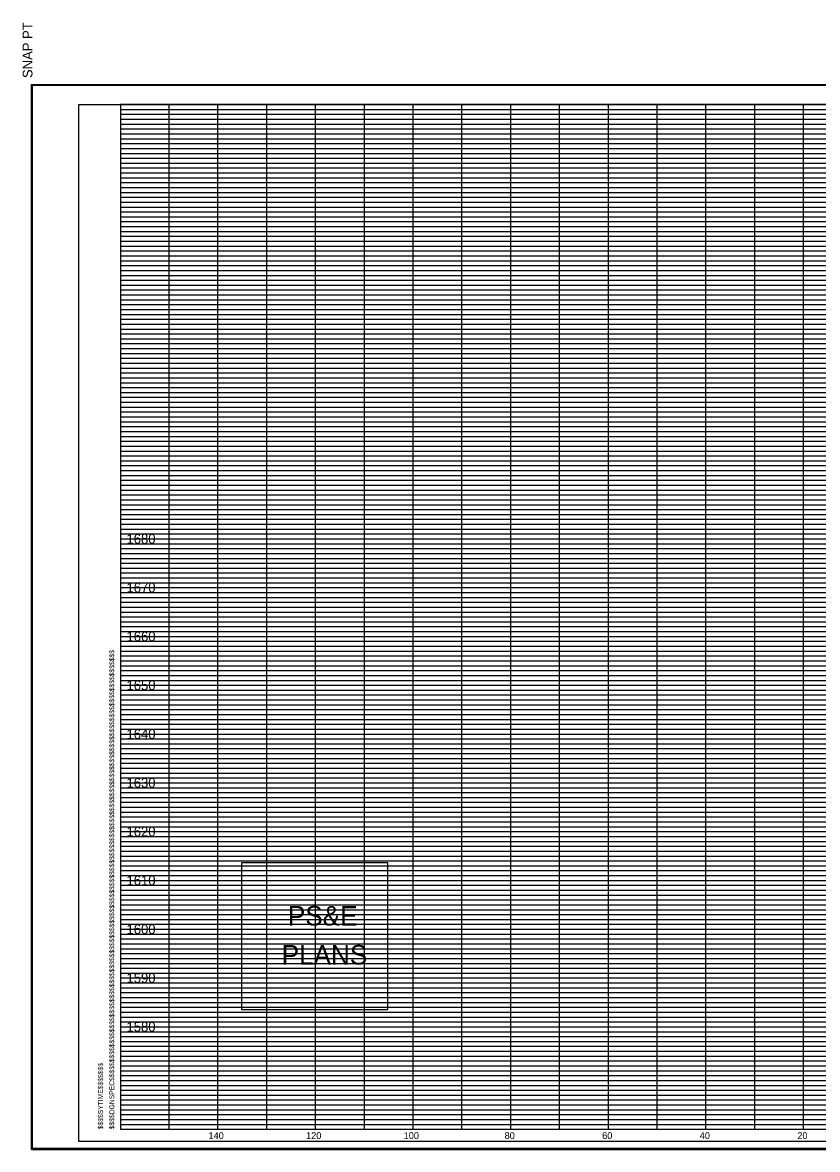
# Model space of a CAD drawing. Extents: x 980 to 1324, y 978 to 1767.
# Drawn here: x 979.9 to 1142.9, y 1265.9 to 1496.8 of the extents above; entities that cross this region are included whole.
import ezdxf

# ---------------------------------------------------------------- set-up
doc = ezdxf.new("R2010")
doc.units = 0
for name, color, linetype in [('DESIGN - SHEET - Corner Text', 7, 'Continuous'), ('DESIGN - SHEET - Light Grid', 7, 'Continuous'), ('DESIGN - SHEET - Linework', 7, 'Continuous'), ('DESIGN - SHEET - Plot Shape', 7, 'Continuous'), ('DESIGN - TYPICAL - Finished Grade and Subgrade', 7, 'Continuous')]:
    doc.layers.add(name, color=color, linetype=linetype)

# ---------------------------------------------------------------- blocks, each defined once
blk = doc.blocks.new('XSTSHT')
at = {"layer": 'DESIGN - SHEET - Light Grid'}
for p, q in [((0, 20.9), (8, 20.9)), ((0, 20.8), (8, 20.8)), ((8, 20.9), (16, 20.9)), ((8, 20.8), (16, 20.8)), ((0, 20.7), (8, 20.7)), ((0, 20.6), (8, 20.6)), ((8, 20.7), (16, 20.7)), ((8, 20.6), (16, 20.6)), ((0, 20.5), (8, 20.5)), ((0, 20.4), (8, 20.4)), ((8, 20.5), (16, 20.5)), ((8, 20.4), (16, 20.4)), ((0, 20.3), (8, 20.3)), ((0, 20.2), (8, 20.2)), ((0, 20.1), (8, 20.1)), ((8, 20.3), (16, 20.3)), ((8, 20.2), (16, 20.2)), ((8, 20.1), (16, 20.1)), ((0, 19.9), (8, 19.9)), ((8, 19.9), (16, 19.9)), ((0, 19.8), (8, 19.8)), ((0, 19.7), (8, 19.7)), ((8, 19.8), (16, 19.8)), ((8, 19.7), (16, 19.7)), ((0, 19.6), (8, 19.6)), ((0, 19.5), (8, 19.5)), ((0, 19.4), (8, 19.4)), ((8, 19.6), (16, 19.6)), ((8, 19.5), (16, 19.5)), ((8, 19.4), (16, 19.4)), ((0, 19.3), (8, 19.3)), ((0, 19.2), (8, 19.2)), ((8, 19.3), (16, 19.3)), ((8, 19.2), (16, 19.2)), ((0, 19.1), (8, 19.1)), ((8, 19.1), (16, 19.1)), ((0, 18.9), (8, 18.9)), ((0, 18.8), (8, 18.8)), ((8, 18.9), (16, 18.9)), ((8, 18.8), (16, 18.8)), ((0, 18.7), (8, 18.7)), ((0, 18.6), (8, 18.6)), ((0, 18.5), (8, 18.5)), ((8, 18.7), (16, 18.7)), ((8, 18.6), (16, 18.6)), ((8, 18.5), (16, 18.5)), ((0, 18.4), (8, 18.4)), ((0, 18.3), (8, 18.3)), ((8, 18.4), (16, 18.4)), ((8, 18.3), (16, 18.3)), ((0, 18.2), (8, 18.2)), ((0, 18.1), (8, 18.1)), ((8, 18.2), (16, 18.2)), ((8, 18.1), (16, 18.1)), ((0, 17.9), (8, 17.9)), ((0, 17.8), (8, 17.8)), ((8, 17.9), (16, 17.9)), ((8, 17.8), (16, 17.8)), ((0, 17.7), (8, 17.7)), ((0, 17.6), (8, 17.6)), ((8, 17.7), (16, 17.7)), ((8, 17.6), (16, 17.6)), ((0, 17.5), (8, 17.5)), ((0, 17.4), (8, 17.4)), ((8, 17.5), (16, 17.5)), ((8, 17.4), (16, 17.4)), ((0, 17.3), (8, 17.3)), ((0, 17.2), (8, 17.2)), ((0, 17.1), (8, 17.1)), ((8, 17.3), (16, 17.3)), ((8, 17.2), (16, 17.2)), ((8, 17.1), (16, 17.1)), ((0, 16.9), (8, 16.9)), ((8, 16.9), (16, 16.9)), ((0, 16.8), (8, 16.8)), ((0, 16.7), (8, 16.7)), ((8, 16.8), (16, 16.8)), ((8, 16.7), (16, 16.7)), ((0, 16.6), (8, 16.6)), ((0, 16.5), (8, 16.5)), ((0, 16.4), (8, 16.4)), ((8, 16.6), (16, 16.6)), ((8, 16.5), (16, 16.5)), ((8, 16.4), (16, 16.4)), ((0, 16.3), (8, 16.3)), ((0, 16.2), (8, 16.2)), ((8, 16.3), (16, 16.3)), ((8, 16.2), (16, 16.2)), ((0, 16.1), (8, 16.1)), ((8, 16.1), (16, 16.1)), ((0, 15.9), (8, 15.9)), ((0, 15.8), (8, 15.8)), ((8, 15.9), (16, 15.9)), ((8, 15.8), (16, 15.8)), ((0, 15.7), (8, 15.7)), ((0, 15.6), (8, 15.6)), ((0, 15.5), (8, 15.5)), ((8, 15.7), (16, 15.7)), ((8, 15.6), (16, 15.6)), ((8, 15.5), (16, 15.5)), ((0, 15.4), (8, 15.4)), ((0, 15.3), (8, 15.3)), ((8, 15.4), (16, 15.4)), ((8, 15.3), (16, 15.3)), ((0, 15.2), (8, 15.2)), ((0, 15.1), (8, 15.1)), ((8, 15.2), (16, 15.2)), ((8, 15.1), (16, 15.1)), ((0, 14.9), (8, 14.9)), ((0, 14.8), (8, 14.8)), ((8, 14.9), (16, 14.9)), ((8, 14.8), (16, 14.8)), ((0, 14.7), (8, 14.7)), ((0, 14.6), (8, 14.6)), ((8, 14.7), (16, 14.7)), ((8, 14.6), (16, 14.6)), ((0, 14.5), (8, 14.5)), ((0, 14.4), (8, 14.4)), ((8, 14.5), (16, 14.5)), ((8, 14.4), (16, 14.4)), ((0, 14.3), (8, 14.3)), ((0, 14.2), (8, 14.2)), ((0, 14.1), (8, 14.1)), ((8, 14.3), (16, 14.3)), ((8, 14.2), (16, 14.2)), ((8, 14.1), (16, 14.1)), ((0, 13.9), (8, 13.9)), ((8, 13.9), (16, 13.9)), ((0, 13.8), (8, 13.8)), ((0, 13.7), (8, 13.7)), ((8, 13.8), (16, 13.8)), ((8, 13.7), (16, 13.7)), ((0, 13.6), (8, 13.6)), ((0, 13.5), (8, 13.5)), ((0, 13.4), (8, 13.4)), ((8, 13.6), (16, 13.6)), ((8, 13.5), (16, 13.5)), ((8, 13.4), (16, 13.4)), ((0, 13.3), (8, 13.3)), ((0, 13.2), (8, 13.2)), ((8, 13.3), (16, 13.3)), ((8, 13.2), (16, 13.2)), ((0, 13.1), (8, 13.1)), ((8, 13.1), (16, 13.1)), ((0, 12.9), (8, 12.9)), ((0, 12.8), (8, 12.8)), ((8, 12.9), (16, 12.9)), ((8, 12.8), (16, 12.8)), ((0, 12.7), (8, 12.7)), ((0, 12.6), (8, 12.6)), ((0, 12.5), (8, 12.5)), ((8, 12.7), (16, 12.7)), ((8, 12.6), (16, 12.6)), ((8, 12.5), (16, 12.5)), ((0, 12.4), (8, 12.4)), ((0, 12.3), (8, 12.3)), ((8, 12.4), (16, 12.4)), ((8, 12.3), (16, 12.3)), ((0, 12.2), (8, 12.2)), ((0, 12.1), (8, 12.1)), ((8, 12.2), (16, 12.2)), ((8, 12.1), (16, 12.1)), ((0, 11.9), (8, 11.9)), ((0, 11.8), (8, 11.8)), ((8, 11.9), (16, 11.9)), ((8, 11.8), (16, 11.8)), ((0, 11.7), (8, 11.7)), ((0, 11.6), (8, 11.6)), ((8, 11.7), (16, 11.7)), ((8, 11.6), (16, 11.6)), ((0, 11.5), (8, 11.5)), ((0, 11.4), (8, 11.4)), ((8, 11.5), (16, 11.5)), ((8, 11.4), (16, 11.4)), ((0, 11.3), (8, 11.3)), ((0, 11.2), (8, 11.2)), ((0, 11.1), (8, 11.1)), ((8, 11.3), (16, 11.3)), ((8, 11.2), (16, 11.2)), ((8, 11.1), (16, 11.1)), ((0, 10.9), (8, 10.9)), ((8, 10.9), (16, 10.9)), ((0, 10.8), (8, 10.8)), ((0, 10.7), (8, 10.7)), ((8, 10.8), (16, 10.8)), ((8, 10.7), (16, 10.7)), ((0, 10.6), (8, 10.6)), ((0, 10.5), (8, 10.5)), ((0, 10.4), (8, 10.4)), ((8, 10.6), (16, 10.6)), ((8, 10.5), (16, 10.5)), ((8, 10.4), (16, 10.4)), ((0, 10.3), (8, 10.3)), ((0, 10.2), (8, 10.2)), ((8, 10.3), (16, 10.3)), ((8, 10.2), (16, 10.2)), ((0, 10.1), (8, 10.1)), ((8, 10.1), (16, 10.1)), ((0, 9.9), (8, 9.9)), ((0, 9.8), (8, 9.8)), ((0, 9.7), (8, 9.7)), ((8, 9.9), (16, 9.9)), ((8, 9.8), (16, 9.8)), ((8, 9.7), (16, 9.7)), ((0, 9.6), (8, 9.6)), ((0, 9.5), (8, 9.5)), ((8, 9.6), (16, 9.6)), ((8, 9.5), (16, 9.5)), ((0, 9.4), (8, 9.4)), ((0, 9.3), (8, 9.3)), ((8, 9.4), (16, 9.4)), ((8, 9.3), (16, 9.3)), ((0, 9.2), (8, 9.2)), ((0, 9.1), (8, 9.1)), ((8, 9.2), (16, 9.2)), ((8, 9.1), (16, 9.1)), ((0, 8.9), (8, 8.9)), ((0, 8.8), (8, 8.8)), ((8, 8.9), (16, 8.9)), ((8, 8.8), (16, 8.8)), ((0, 8.7), (8, 8.7)), ((0, 8.6), (8, 8.6)), ((8, 8.7), (16, 8.7)), ((8, 8.6), (16, 8.6)), ((0, 8.5), (8, 8.5)), ((0, 8.4), (8, 8.4)), ((8, 8.5), (16, 8.5)), ((8, 8.4), (16, 8.4)), ((0, 8.3), (8, 8.3)), ((0, 8.2), (8, 8.2)), ((0, 8.1), (8, 8.1)), ((8, 8.3), (16, 8.3)), ((8, 8.2), (16, 8.2)), ((8, 8.1), (16, 8.1)), ((0, 7.9), (8, 7.9)), ((8, 7.9), (16, 7.9)), ((0, 7.8), (8, 7.8)), ((0, 7.7), (8, 7.7)), ((8, 7.8), (16, 7.8)), ((8, 7.7), (16, 7.7)), ((0, 7.6), (8, 7.6)), ((0, 7.5), (8, 7.5)), ((0, 7.4), (8, 7.4)), ((8, 7.6), (16, 7.6)), ((8, 7.5), (16, 7.5)), ((8, 7.4), (16, 7.4)), ((0, 7.3), (8, 7.3)), ((0, 7.2), (8, 7.2)), ((8, 7.3), (16, 7.3)), ((8, 7.2), (16, 7.2)), ((0, 7.1), (8, 7.1)), ((8, 7.1), (16, 7.1)), ((0, 6.9), (8, 6.9)), ((0, 6.8), (8, 6.8)), ((0, 6.7), (8, 6.7)), ((8, 6.9), (16, 6.9)), ((8, 6.8), (16, 6.8)), ((8, 6.7), (16, 6.7)), ((0, 6.6), (8, 6.6)), ((0, 6.5), (8, 6.5)), ((8, 6.6), (16, 6.6)), ((8, 6.5), (16, 6.5)), ((0, 6.4), (8, 6.4)), ((0, 6.3), (8, 6.3)), ((8, 6.4), (16, 6.4)), ((8, 6.3), (16, 6.3)), ((0, 6.2), (8, 6.2)), ((0, 6.1), (8, 6.1)), ((8, 6.2), (16, 6.2)), ((8, 6.1), (16, 6.1)), ((0, 5.9), (8, 5.9)), ((0, 5.8), (8, 5.8)), ((8, 5.9), (16, 5.9)), ((8, 5.8), (16, 5.8)), ((0, 5.7), (8, 5.7)), ((0, 5.6), (8, 5.6)), ((8, 5.7), (16, 5.7)), ((8, 5.6), (16, 5.6)), ((0, 5.5), (8, 5.5)), ((0, 5.4), (8, 5.4)), ((8, 5.5), (16, 5.5)), ((8, 5.4), (16, 5.4)), ((0, 5.3), (8, 5.3)), ((0, 5.2), (8, 5.2)), ((0, 5.1), (8, 5.1)), ((8, 5.3), (16, 5.3)), ((8, 5.2), (16, 5.2)), ((8, 5.1), (16, 5.1)), ((0, 4.9), (8, 4.9)), ((8, 4.9), (16, 4.9)), ((0, 4.8), (8, 4.8)), ((0, 4.7), (8, 4.7)), ((8, 4.8), (16, 4.8)), ((8, 4.7), (16, 4.7)), ((0, 4.6), (8, 4.6)), ((0, 4.5), (8, 4.5)), ((0, 4.4), (8, 4.4)), ((8, 4.6), (16, 4.6)), ((8, 4.5), (16, 4.5)), ((8, 4.4), (16, 4.4)), ((0, 4.3), (8, 4.3)), ((0, 4.2), (8, 4.2)), ((8, 4.3), (16, 4.3)), ((8, 4.2), (16, 4.2)), ((0, 4.1), (8, 4.1)), ((8, 4.1), (16, 4.1)), ((0, 3.9), (8, 3.9)), ((0, 3.8), (8, 3.8)), ((0, 3.7), (8, 3.7)), ((8, 3.9), (16, 3.9)), ((8, 3.8), (16, 3.8)), ((8, 3.7), (16, 3.7)), ((0, 3.6), (8, 3.6)), ((0, 3.5), (8, 3.5)), ((8, 3.6), (16, 3.6)), ((8, 3.5), (16, 3.5)), ((0, 3.4), (8, 3.4)), ((0, 3.3), (8, 3.3)), ((8, 3.4), (16, 3.4)), ((8, 3.3), (16, 3.3)), ((0, 3.2), (8, 3.2)), ((0, 3.1), (8, 3.1)), ((8, 3.2), (16, 3.2)), ((8, 3.1), (16, 3.1)), ((0, 2.9), (8, 2.9)), ((0, 2.8), (8, 2.8)), ((8, 2.9), (16, 2.9)), ((8, 2.8), (16, 2.8)), ((0, 2.7), (8, 2.7)), ((0, 2.6), (8, 2.6)), ((8, 2.7), (16, 2.7)), ((8, 2.6), (16, 2.6)), ((0, 2.5), (8, 2.5)), ((0, 2.4), (8, 2.4)), ((8, 2.5), (16, 2.5)), ((8, 2.4), (16, 2.4)), ((0, 2.3), (8, 2.3)), ((0, 2.2), (8, 2.2)), ((0, 2.1), (8, 2.1)), ((8, 2.3), (16, 2.3)), ((8, 2.2), (16, 2.2)), ((8, 2.1), (16, 2.1)), ((0, 1.9), (8, 1.9)), ((8, 1.9), (16, 1.9)), ((0, 1.8), (8, 1.8)), ((0, 1.7), (8, 1.7)), ((8, 1.8), (16, 1.8)), ((8, 1.7), (16, 1.7)), ((0, 1.6), (8, 1.6)), ((0, 1.5), (8, 1.5)), ((0, 1.4), (8, 1.4)), ((8, 1.6), (16, 1.6)), ((8, 1.5), (16, 1.5)), ((8, 1.4), (16, 1.4)), ((0, 1.3), (8, 1.3)), ((0, 1.2), (8, 1.2)), ((8, 1.3), (16, 1.3)), ((8, 1.2), (16, 1.2)), ((0, 1.1), (8, 1.1)), ((8, 1.1), (16, 1.1)), ((0, 0.9), (8, 0.9)), ((0, 0.8), (8, 0.8)), ((0, 0.7), (8, 0.7)), ((8, 0.9), (16, 0.9)), ((8, 0.8), (16, 0.8)), ((8, 0.7), (16, 0.7)), ((0, 0.6), (8, 0.6)), ((0, 0.5), (8, 0.5)), ((8, 0.6), (16, 0.6)), ((8, 0.5), (16, 0.5)), ((0, 0.4), (8, 0.4)), ((0, 0.3), (8, 0.3)), ((8, 0.4), (16, 0.4)), ((8, 0.3), (16, 0.3)), ((0, 0.2), (8, 0.2)), ((0, 0.1), (8, 0.1)), ((8, 0.2), (16, 0.2)), ((8, 0.1), (16, 0.1))]:
    blk.add_line(p, q, dxfattribs=at)
at = {"layer": 'DESIGN - SHEET - Linework'}
for p, q in [((-1.823, -0.414), (-1.823, 21.414)), ((-1.823, 21.414), (32.217, 21.414)), ((1, 0), (1, 21)), ((2, 0), (2, 21)), ((3, 0), (3, 21)), ((4, 0), (4, 21)), ((5, 0), (5, 21)), ((6, 0), (6, 21)), ((7, 0), (7, 21)), ((8, 0), (8, 21)), ((9, 0), (9, 21)), ((10, 0), (10, 21)), ((11, 0), (11, 21)), ((12, 0), (12, 21)), ((13, 0), (13, 21)), ((14, 0), (14, 21)), ((0, 20), (28, 20)), ((0, 19), (32, 19)), ((0, 18), (32, 18)), ((0, 17), (32, 17)), ((0, 16), (32, 16)), ((0, 15), (32, 15)), ((0, 14), (32, 14)), ((0, 13), (32, 13)), ((0, 12), (32, 12)), ((0, 11), (32, 11)), ((0, 10), (32, 10)), ((0, 9), (32, 9)), ((0, 8), (32, 8)), ((0, 7), (32, 7)), ((0, 6), (32, 6)), ((0, 5), (32, 5)), ((0, 4), (32, 4)), ((0, 3), (32, 3)), ((0, 2), (32, 2)), ((0, 1), (32, 1)), ((-1.823, -0.414), (32.217, -0.414))]:
    blk.add_line(p, q, dxfattribs=at)
blk.add_lwpolyline([(0, 21), (0, 0), (32, 0), (32, 21), (0, 21)], dxfattribs=at)
at = {"layer": 'DESIGN - SHEET - Plot Shape'}
for points in [[(-1.803, 21.394), (32.197, 21.394), (32.197, -0.394), (-1.803, -0.394)], [(-0.85, 21), (32, 21), (32, -0.25), (-0.85, -0.25)]]:
    blk.add_lwpolyline(points, close=True, dxfattribs=at)
at = {"layer": 'DESIGN - SHEET - Corner Text'}
for s, height, p in [('  SNAP PT', 0.2, (-1.803, 21.394)), ('$$$$DGNSPEC$$$$$$$$$$$$$$$$$$$$$$$$$$$$$$$$$$$$$$$$$$$$$$$$$$$$$$$$$$$$$$$$$$$$$$$$$$$$$$$$$$$$$$$$$$$$$$$$$$$$$$$$$$$$$$$$$$$', 0.100002, (-0.126, 0)), ('$$$$SYTIME$$$$$$$', 0.1, (-0.358, 0))]:
    blk.add_text(s, height=height, rotation=90, dxfattribs=at).set_placement(p)

msp = doc.modelspace()

# ---------------------------------------------------------------- linework, layer by layer
at = {"layer": 'DESIGN - SHEET - Corner Text'}
msp.add_lwpolyline([(1024.81, 1324.57), (1024.81, 1294.57), (1054.81, 1294.57), (1054.81, 1324.57)], close=True, dxfattribs=at)
at = {"layer": 'DESIGN - SHEET - Plot Shape'}
msp.add_lwpolyline([(991.5, 1480), (1320, 1480), (1320, 1267.5), (991.5, 1267.5)], close=True, dxfattribs=at)

# ---------------------------------------------------------------- block references
at = {"layer": 'DESIGN - TYPICAL - Finished Grade and Subgrade', "xscale": 10, "yscale": 10}
msp.add_blockref('XSTSHT', (1000, 1270), dxfattribs=at)

# ---------------------------------------------------------------- texts
at = {"layer": 'DESIGN - SHEET - Corner Text'}
for s, height, p in [('1680', 2, (1001.25, 1390)), ('1670', 2, (1001.25, 1380)), ('1660', 2, (1001.25, 1370)), ('1650', 2, (1001.25, 1360)), ('1640', 2, (1001.25, 1350)), ('1630', 2, (1001.25, 1340)), ('1620', 2, (1001.25, 1330)), ('1610', 2, (1001.25, 1320)), ('PS&E', 4, (1034.33, 1311.75)), ('1600', 2, (1001.25, 1310)), ('PLANS', 4, (1033.05, 1303.75)), ('1590', 2, (1001.25, 1300)), ('1580', 2, (1001.25, 1290)), ('140', 1.4, (1018.06, 1268)), ('120', 1.4, (1038.06, 1268)), ('100', 1.4, (1058.06, 1268)), ('80', 1.4, (1078.74, 1268)), ('60', 1.4, (1098.74, 1268)), ('40', 1.4, (1118.74, 1268)), ('20', 1.4, (1138.74, 1268))]:
    msp.add_text(s, height=height, dxfattribs=at).set_placement(p)

doc.saveas('drawing.dxf')
